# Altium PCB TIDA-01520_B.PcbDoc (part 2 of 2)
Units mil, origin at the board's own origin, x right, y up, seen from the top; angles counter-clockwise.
Board outline 2952.76 x 2362.2 mil, 2 copper layers (Top Layer, Bottom Layer), stack 62 mil thick; 118 components, 52 nets, 283 pads, 133 vias.
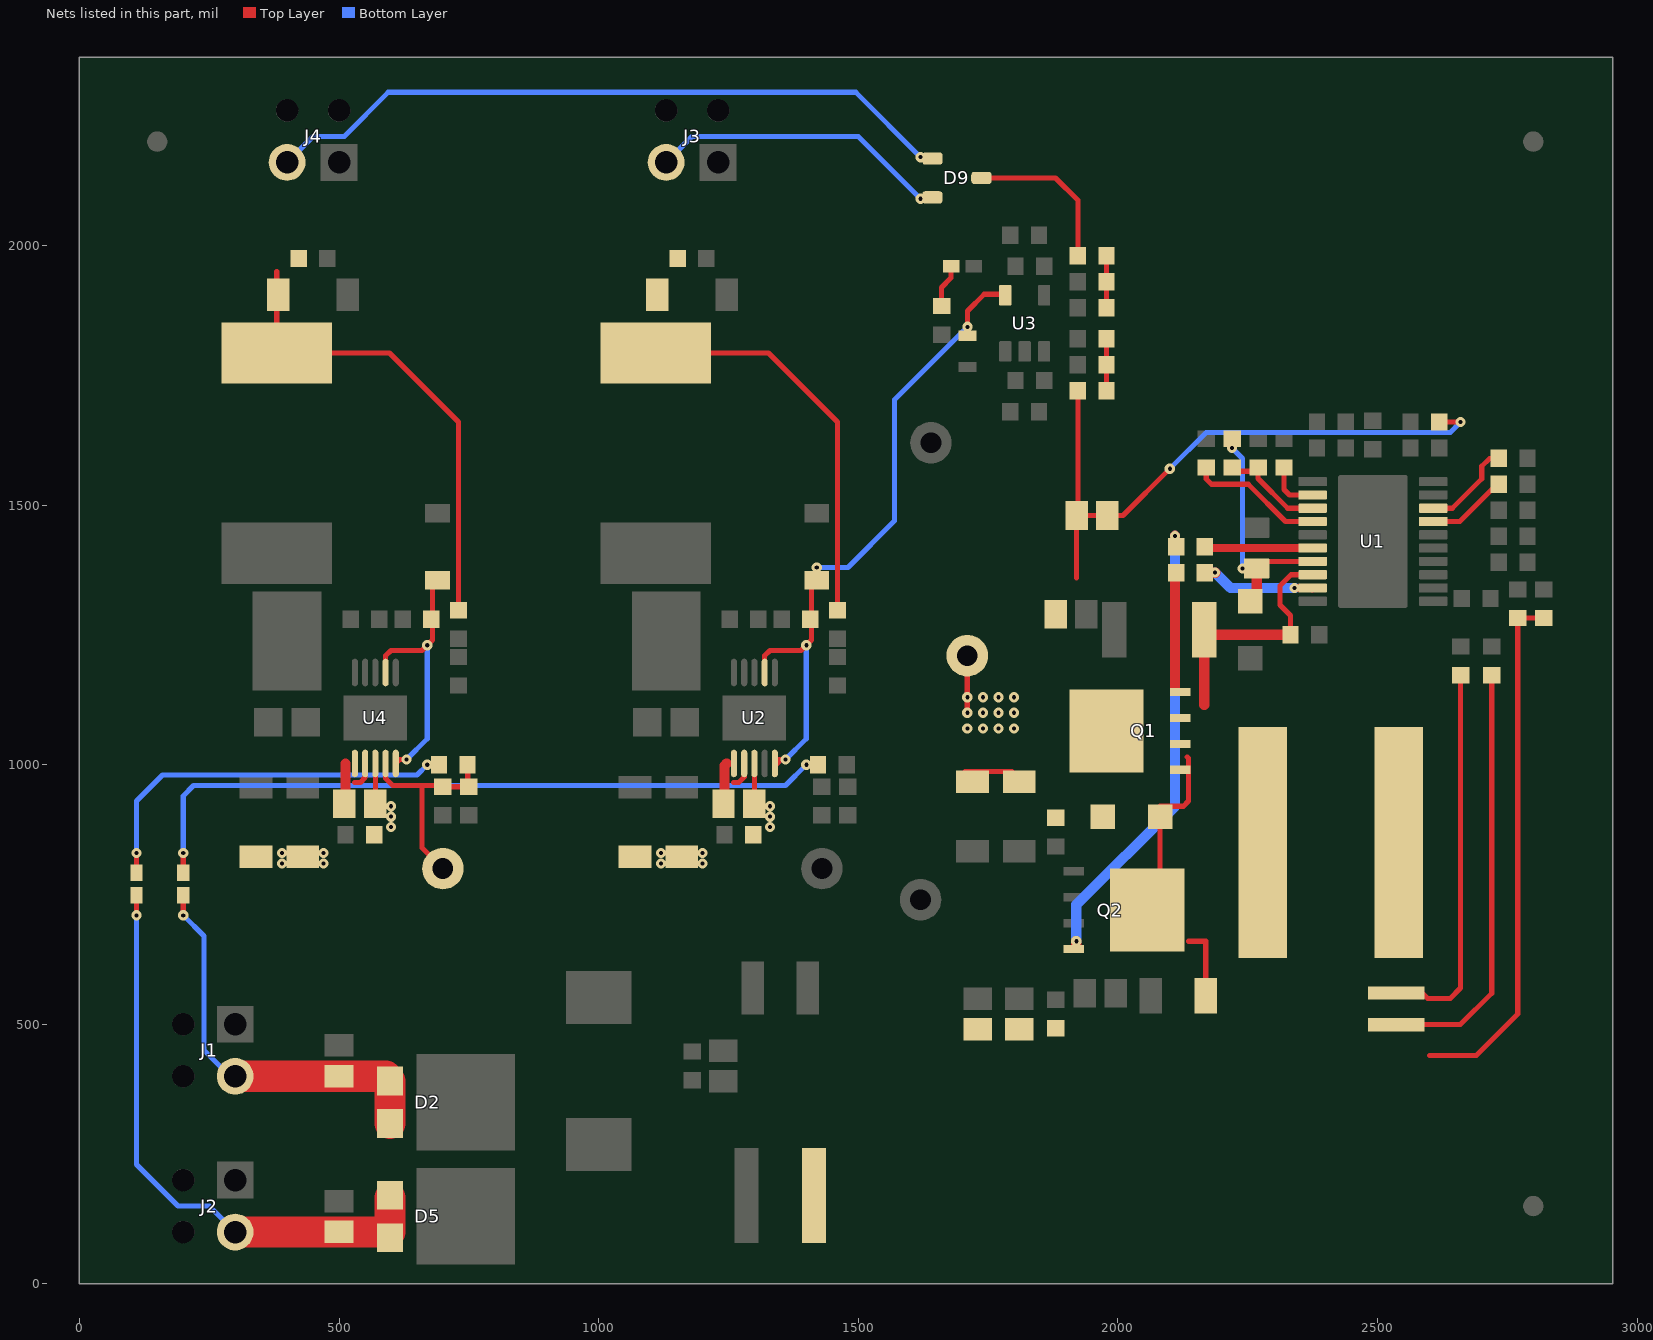
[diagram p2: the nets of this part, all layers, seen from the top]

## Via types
v1: diameter 19.68, hole 7.87, Top Layer to Bottom Layer, tented both sides, 124 vias
v2: diameter 19.68, hole 7.87, Top Layer to Bottom Layer, 9 vias

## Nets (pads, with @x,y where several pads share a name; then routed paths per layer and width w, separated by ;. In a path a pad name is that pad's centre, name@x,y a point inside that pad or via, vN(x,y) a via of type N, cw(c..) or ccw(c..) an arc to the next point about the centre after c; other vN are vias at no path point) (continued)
NetC40_1: C40.1 R36.1 R37.1 TP5.1 U4.9 | length 420.8
  Top Layer w10: U4.9@589.69,1002.4 589.69,973.79 603.48,960 R37.1@702.44,960 ; 660,960 660,840 TP5.1@700,800 ; R37.1@697.44,955 R37.1@700,957.56 C40.1@750,957.56 C40.1@752.56,960.12 ; C40.1@748.05,960.12 R36.1@748.05,1000
NetD8_1: D8.1 R23.2 | length 1373.2
  Top Layer w10: D8.1@200,791.65 v1(200,830)
  Bottom Layer w10: v1(200,830) 200,940 220,960 1360.04,960.04 v1(1400,1000)
NetD9_3: D9.3 R26.2 | length 310.5
  Top Layer w10: D9.3@1737.24,2130 1880,2130 1922.91,2087.09 1922.91,2030 R26.2@1922.91,1980
NetD11_2: D11.2 R29.2 | length 90
  Top Layer w10: R29.2@1660.47,1877.56 1660.47,1919.31 1678.82,1937.66 D11.2@1678.82,1960
NetD13_1: D13.1 R36.2 | length 749.8
  Top Layer w10: D13.1@110,791.65 v1(110,830) ; v1(670,1000) R36.2@692.44,1000
  Bottom Layer w10: v1(110,830) 110,930 160,980 650,980 v1(670,1000)
NetL1_1: L1.1 R2.2 R9.2 | length 688.9
  Top Layer w10: R2.2@2586.14,560.51 2596.65,550 2640,550 2660,570 R9.2@2660,1172.44
NetQ1_4: Q1.4 R12.2 | length 230
  Top Layer w20: Q1.4@2110,1145 R12.2@2110,1375
NetQ2_4: Q2.4 R11.2 | length 887.2
  Top Layer w20: Q2.4@1920,650.43 v1(1920,660) ; R11.2@2110,1422.44 v1(2110,1440.67)
  Bottom Layer w20: v1(1920,660) 1920,730 2110,920 v1(2110,1440.67)
NetR11_1: R11.1 U1.16 | length 208.6
  Top Layer w10: R11.1@2167.56,1420 R11.1@2170.35,1417.2
  Top Layer w16: R11.1@2170.35,1417.2 U1.16@2375,1417.2
NetR12_1: R12.1 U1.19 | length 220
  Top Layer w10: U1.19@2374.57,1340 U1.19@2375,1340.43
  Top Layer w16: v1(2340.26,1340.43) 2374.13,1340.43 U1.19@2374.57,1340
  Top Layer w20: R12.1@2167.56,1370 v1(2187.24,1370)
  Bottom Layer w20: v1(2187.24,1370) 2216.81,1340.43 v1(2340.26,1340.43)
NetR16_1: R16.1 R17.1 U1.13 | length 195.3
  Top Layer w10: R17.1@2220,1565.24 R16.1@2260,1565.24 ; R16.1@2263.94,1575.24 2270,1569.18 2270,1551.14 2327.17,1493.98 U1.13@2375,1493.98
NetR18_2: R18.2 U1.14 | length 256.6
  Top Layer w10: R18.2@2163.94,1565.24 2170,1559.18 2170,1550 2180,1540 2251.14,1540 2322.76,1468.39 U1.14@2375,1468.39
NetR19_2: R19.2 U1.12 | length 107.1
  Top Layer w10: R19.2@2313.94,1575.24 2320,1569.18 2320,1530 2330.43,1519.57 U1.12@2375,1519.57
NetR20_2: R20.2 U1.8 | length 194.2
  Top Layer w10: U1.8@2607.28,1493.98 2643.98,1493.98 2700.87,1550.87 2700.87,1574.73 2716.14,1590 R20.2@2733.58,1590 R20.2@2743.58,1580
NetR21_1: R21.1 U2.6 U2.7 | length 114.9
  Top Layer w10: 1260,965.98 1270,965.98 1280.32,976.3 U2.7@1280.32,1002.4
  Top Layer w20: R21.1@1242.44,940 1242.44,998.03 1246.81,1002.4
NetR26_1: R26.1 R27.2 R28.1 | length 100
  Top Layer w10: R27.2@1978.03,1880 R28.1@1978.03,1930 R26.1@1978.03,1980
NetR30_1: R30.1 R31.1 R33.2 | length 100
  Top Layer w10: R31.1@1978.03,1720 R30.1@1978.03,1770 R33.2@1978.03,1820
NetR34_1: R34.1 U4.6 U4.7 | length 113.8
  Top Layer w10: 530,965.98 541.14,965.98 550.32,975.16 U4.7@550.32,1002.4
  Top Layer w20: 512.4,1002.4 R34.1@512.44,940
SS: C18.1 U1.7 | length 171.4
  Top Layer w10: U1.7@2611.14,1472.24 U1.7@2607.28,1468.39 2658.39,1468.39 2730,1540 C18.1@2743.58,1540
SW_BOOST: C11.2 D1.2 L1.2 Q1.1 Q1.2 Q1.3 Q2.5 R1.1 R4.2 U1.18 | length 902.4
  Top Layer w10: Q2.5@2057.83,750 2081.26,773.43 2081.26,920 2126.14,920 2136.14,930 2136.14,1012.28 2133.43,1015 ; 2136.14,660 2169.29,660 R4.2@2169.29,580 ; C11.2@2332.44,1250 2332.44,1287.56 2312.44,1307.56 2312.44,1344.74 2333.72,1366.02 U1.18@2375,1366.02
  Top Layer w20: 2166.61,1115 R1.1@2166.61,1260 ; R1.1@2190,1250 C11.2@2335,1250
V+: C3.1 C4.1 C5.1 L2.2 R2.1 R5.2 R6.2 R8.2 | length 1791.1
  Top Layer w10: R2.1@2586.14,499.49 2659.49,499.49 2720,560 2720,1162.44 R8.2@2710,1172.44 ; 2600,440 2690,440 2770,520 R6.2@2770,1282.44 R5.2@2820,1282.44
VCC: C12.2 D4.2 R17.2 U1.17 | length 395.3
  Top Layer w10: C12.2@2274.92,1391.61 U1.17@2375,1391.61
  Top Layer w20: D4.2@2267.14,1327.26 C12.2@2267.14,1377.83
  Bottom Layer w10: v1@2218,1606 v1@2221,1609 ; v1(2220,1610) 2240,1590 v1(2240,1377.83)
VCC_B1: C19.1 C29.1 D6.2 U2.2 U2.10 U3.5 | length 1261.1
  Top Layer w10: U2.2@1319.69,1177.6 1319.69,1209.69 1330,1220 1390,1220 v1(1400,1230) 1410,1240 D6.2@1410,1345.53 ; U2.10@1339.37,1002.4 1341.77,1000 v1@1351.77,1010 ; 1346.97,1010 v1@1351.77,1010 ; v1(1360,1010) v1@1351.77,1010 ; C29.1@1710.47,1825.86 v1(1710.47,1843.36) 1710.47,1873.73 1742.74,1906 1781.2,1906 U3.5@1783.07,1904.13
  Bottom Layer w10: v1(1360,1010) 1400,1050 v1(1400,1230) ; v1(1420,1380) 1480,1380 1570,1470 1570,1702.89 v1(1710.47,1843.36)
VCC_B2: C31.1 D10.2 U4.2 U4.10 | length 515
  Top Layer w10: U4.2@589.69,1177.6 589.69,1209.69 600,1220 660,1220 680,1240 680,1280 680,1345.53 D10.2@690,1355.53 ; U4.10@609.37,1002.4 616.97,1010 v1(630,1010)
  Bottom Layer w10: v1(630,1010) 670,1050 v1(670,1230)
VIN1: C30.1 D2.1 D2.2 D8.2 J1.2 | length 767.5
  Top Layer w10: v1(200,710) D8.2@200,748.35
  Top Layer w60: J1.2@300,400 D2.2@590,400 ; D2.1@597.95,309.06 D2.2@597.95,390.94
  Bottom Layer w10: v1(200,710) 240,670 240,450 290,400 J1.2@300,400
VIN2: C41.1 D5.1 D5.2 D13.2 J2.2 | length 1126.4
  Top Layer w10: v1(110,709.96) D13.2@110,748.35
  Top Layer w60: J2.2@300,100 597.95,100 D5.2@597.95,166.22
  Bottom Layer w10: v1(110,709.96) 110,230 190,150 250,150 J2.2@300,100
VOUT_B1: C24.1 C25.1 D9.2 J3.2 L3.2 R22.2 | length 1325.5
  Top Layer w10: L3.2@1110,1792.91 1327.09,1792.91 1460,1660 R22.2@1460,1300
  Bottom Layer w10: J3.2@1130,2160 1180,2210 1500,2210 v1(1620,2090)
VOUT_B2: C37.1 C38.1 D9.1 J4.2 L4.2 R35.2 | length 2255.5
  Top Layer w10: 380,1950 L4.2@380,1802.91 ; L4.2@384.02,1806.93 L4.2@380,1802.91 ; R35.2@730,1300 730,1660 597.09,1792.91 L4.2@380,1792.91 L4.2@380,1802.91
  Bottom Layer w10: J4.2@400,2160 450,2210 510,2210 595,2295 1495,2295 v1(1620,2170)
VOUT_BOOST: C6.1 C7.1 C8.1 C9.1 C21.1 C22.1 C23.1 C34.1 C35.1 C36.1 D1.1 Q1.5 R7.1 R7.2 R10.2 R21.2 R31.2 R34.2 TP1.1 U2.8 U4.8 | length 1561.4
  Top Layer w10: R34.2@570,920 U4.8@570,1002.4 ; R21.2@1300,920 U2.8@1300,1002.4 ; C7.1@1706.14,986.93 C8.1@1796.14,986.93 ; v1(1710,1100) TP1.1@1710,1190 ; 1920,1360 1920.47,1360.47 R7.2@1920.47,1480 ; R31.2@1922.91,1720 1922.91,1482.44 R7.2@1920.47,1480 ; v1(2100,1570) 2010,1480 R7.1@1979.53,1480 R7.2@1920.47,1480 ; R10.2@2618.7,1660 v1(2660,1660)
  Bottom Layer w10: v1(2100,1570) 2170,1640 2640,1640 v1(2660,1660)
  other v1: 390,810 470,810 1120,810 1200,810 390,830 470,830 1120,830 1200,830 600,880 1330,880 600,900 1330,900 600,920 1330,920 1710,1070 1740,1070 1770,1070 1800,1070 1740,1100 1770,1100 1800,1100 1710,1130 1740,1130 1770,1130 1800,1130
pads on no net: FID1.1 FID2.1 FID3.1 J1.MH1 J1.MH2 J2.MH1 J2.MH2 J3.MH1 J3.MH2 J4.MH1 J4.MH2 U1.1 U1.21@2491.14,1430 U2.0 U4.0

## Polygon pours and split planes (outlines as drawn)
NetC1_1 on Bottom Layer "BOTTOM_LAYER_NETC1_1_P021" (solid, remove dead copper, pour order 21): 1270,50 1310,90 1310,350 1250,410 390,410 360,380 360,90 400,50
VOUT_BOOST on Bottom Layer "BOTTOM_LAYER_VOUT_BOOST_P009" (solid, remove dead copper, pour order 9): 2080,920 2000,840 1736.14,840 1706.14,810 1536.14,640 270,640 220,690 220,950 1380,950 1570,1140 1570,1418.84 1591.16,1440 2080,1440
GND on Bottom Layer "BOTTOM_LAYER_GND_P012" (solid, remove dead copper, pour order 12): 900,980 180,980 50,1110 50,2110 130,2190 900,2190
GND on Bottom Layer "BOTTOM_LAYER_GND_P010" (solid, remove dead copper, pour order 10): 1550,980 870,980 870,2190 1480,2190 1550,2120
GND on Bottom Layer "BOTTOM_LAYER_GND_P019" (solid, remove dead copper, pour order 19): 2900,100 2850,50 1430,50 1380,100 1380,520 1580,720 1580,2260 1630,2310 2850,2310 2900,2260
VOUT_BOOST on Top Layer "TOP_LAYER_VOUT_BOOST_P003" (solid, remove dead copper, pour order 3): 640,910 580,970 560,970 550,960 550,879.33 520.67,850 300,850 300,740 570,740 640,810
NetR21_1 on Top Layer "TOP_LAYER_NETR21_1_P001" (solid, remove dead copper, pour order 1): 1220,920 1220,1000.49 1249.51,1030 1265.16,1030 1265.16,955.65 1259.51,950 1259.51,920
NetR34_1 on Top Layer "TOP_LAYER_NETR34_1_P000" (solid, remove dead copper, pour order 0): 490,920 490,1000 520,1030 535.16,1030 535.16,955.16 530,950 530,920
BAT_GND on Top Layer "TOP_LAYER_BAT_GND_P020" (solid, remove dead copper, pour order 20): 1260,430 1310,480 1310,600 1290,620 100,620 50,570 50,100 100,50 530,50 530,430
NetC1_1 on Top Layer "TOP_LAYER_NETC1_1_P017" (solid, remove dead copper, pour order 17): 1270,50 1310,90 1310,360 1260,410 570,410 570,50
VOUT_BOOST on Top Layer "TOP_LAYER_VOUT_BOOST_P008" (solid, remove dead copper, pour order 8): 2060,950 1990,880 1750,880 1650,980 1650,1340 1690,1380 2020,1380 2060,1340
SW_BOOST on Top Layer "TOP_LAYER_SW_BOOST_P014" (solid, remove dead copper, pour order 14): 2240,1120 2090,1120 2080,1110 2080,940 1980,840 1980,620 2000,600 2260,600 2290,630 2290,1070
GND on Top Layer "TOP_LAYER_GND_P013" (solid, remove dead copper, pour order 13): 2770,1370.09 2770,1610.67 2760.67,1620 2720,1620 2690,1590 2690,1550 2659.57,1519.57 2625.59,1519.57 2625.59,1615.59 2670,1660 2670,1690 2350,1690 2340,1680 2340,1610 2140,1610 2090,1660 2090,1780 2140,1830 2850,1830 2900,1780 2900,1380 2890.09,1370.09
GND on Top Layer "TOP_LAYER_GND_P011" (solid, remove dead copper, pour order 11): 1959.78,530 1410,530 1300,640 100,640 50,690 50,2260 100,2310 1580,2310 1630,2260 1630,970 1740,860 1959.78,860
V+ on Top Layer "TOP_LAYER_NETC3_1_P015" (solid, remove dead copper, pour order 15): 2610,510 1430,510 1380,460 1380,100 1430,50 1480,50 1730,300 2520,300 2610,390
NetL1_1 on Top Layer "TOP_LAYER_NETL1_1_P016" (solid, remove dead copper, pour order 16): 2610,660 2610,540 2480,540 2480,660
NetC33_2 on Top Layer "TOP_LAYER_NETC33_2_P007" (solid, remove dead copper, pour order 7): 520.31,1210.31 490,1240.63 490,1470 270,1470 270,1350 330,1290 330,1140 480,1140 499.13,1140 500,1140 508.04,1148.04 540,1148.04 540,1210.31
NetC20_2 on Top Layer "TOP_LAYER_NETC20_2_P006" (solid, remove dead copper, pour order 6): 1220,1249.99 1220,1470 1000,1470 1000,1350 1059.06,1290.95 1059.06,1140 1210,1140 1229.13,1140 1230,1140 1238.04,1148.04 1270,1148.04 1270,1219.81 1250,1220
VOUT_B2 on Top Layer "TOP_LAYER_VOUT_B2_P004" (solid, remove dead copper, pour order 4): 490,1730 490,1850 450,1890 450,2180 250.01,2180 250,1990 250,1730
VOUT_B1 on Top Layer "TOP_LAYER_VOUT_B1_P005" (solid, remove dead copper, pour order 5): 1220,1730 1220,1850 1180,1890 1180,2180 980.01,2180 980,1990 980,1730
VOUT_BOOST on Top Layer "TOP_LAYER_VOUT_BOOST_P002" (solid, remove dead copper, pour order 2): 1370,905.62 1305.62,970 1290,970 1280,960 1280,879.33 1250.67,850 1030,850 1030,740 1318.39,740 1370,791.61

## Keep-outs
Keep-Out Layer:
  text ".Layer_Name" at 577,-858.49 h60

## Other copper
Top Layer:
  text ".Layer_Name" at 577,-858.49 h60
Bottom Layer:
  text ".Layer_Name" at 577,-858.49 h60

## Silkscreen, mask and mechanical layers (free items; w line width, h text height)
Top Overlay:
  lines w8: 1570,1535.86 2020.47,1535.86 2020.47,2205.86 1570,2205.86 1570,1535.86
  text "+" at 390,2310 h40
  text "-" at 490,2310 h40
  text "+" at 1120,2310 h40
  text "-" at 1220,2310 h40
  text "CH2" at 600,2260 h40
  text "CH1" at 1330,2260 h40
  text "Pre-Boost Control" at 1550,2230 h30
  text "'.PRJ_Number' Rev.'.PCB_Rev'" at 2290,2050 h40
  text "'.PRJ_Title'" at 2300,1980 h30
  text "-" at 110,490 h40
  text "IN1" at 30,430 h40
  text "+" at 110,370 h40
  text "6-18V" at 30,280 h30
  text "-" at 110,190 h40
  text "IN2" at 30,130 h40
  text "+" at 110,70 h40
  text ".Layer_Name" at 577,-858.49 h60
Bottom Overlay:
  text ".Layer_Name" at 577,-858.49 h60
Top Paste:
  text ".Layer_Name" at 577,-858.49 h60
Bottom Paste:
  text ".Layer_Name" at 577,-858.49 h60
Top Solder:
  text ".Layer_Name" at 577,-858.49 h60
  text ".Layer_Name" at 577,-858.49 h60
Bottom Solder:
  text ".Layer_Name" at 577,-858.49 h60
Drill Guide:
  text ".Layer_Name" at 577,-858.49 h60
M1 Board Outline:
  the board outline again, w10
  text ".Layer_Name" at 577,-858.49 h60
M2 Board Dimensions:
  rectangle: 0,-275 125,-150
  rectangle: 125,-400 500,-275
  lines w7: 0,-275 1000,-275 ; 125,-400 125,-150 ; 250,-400 250,-150 ; 500,-400 500,-150 ; 750,-400 750,-150 ; 0,-400 1000,-400 1000,-150 0,-150 0,-400
  text ".Layer_Name" at 577,-858.49 h60
M3 3D STEP Top:
  text ".Layer_Name" at 577,-858.49 h60
M4 3D STEP Bottom:
  text ".Layer_Name" at 577,-858.49 h60
M5 Assembly Top:
  lines w10: -292,-930.17 6308,-930.17 ; -292,-726.83 6310,-726.83 ; -292,-523.5 -292,-1133.5 3713,-1133.5 6310,-1133.5 6310,-523.5 -291.5,-523.5 -291.5,-1133.5 1284,-1133.5 ; 2173,-1133.5 2173,-523.5 ; 3440,-726.83 3440,-523.5 ; 4280,-726.83 4280,-523.5 ; 4902,-1140 4902,-937.17
  text "COMPONENTS MARKED 'DNP' SHOULD NOT BE POPULATED." at 1153.5,-318.5 h60
  text "ASSEMBLY VARIANT:" at 1153,-434 h60
  text ".VariantName" at 2189,-434 h60
  text "PCB VIEWED FROM TOP SIDE" at -228.5,-655.67 h60
  text "BOARD #:" at 2248,-655.67 h60
  text ".PRJ_Number" at 2793.5,-655.67 h60
  text "REV:" at 3638,-655.67 h60
  text ".PCB_Rev" at 3929.5,-655.67 h60
  text "SVN REV:" at 4476,-655.67 h60
  text ".VersionControl_RevNumber" at 4982,-655.67 h60
  text "TID #:" at 2248,-859 h60
  text ".TID" at 2793.5,-859 h60
  text "PLOT NAME =" at -228.5,-1064.34 h60
  text ".plot_File_Name" at 577,-1064.34 h60
  text "GENERATED    :" at 2250,-1064.34 h60
  text ".Print_Date" at 3119.5,-1064.34 h60
  text ".Print_Time" at 3848.5,-1064.34 h60
  text "TEXAS INSTRUMENTS" at 5113,-1064.34 h60
M6 Assembly Bottom:
  lines w10: -292.5,-727.33 6309.5,-727.33 ; -290.5,-930.67 6309.5,-930.67 ; 1115.5,-1140.5 1115.5,-937.67 ; 1737.5,-727.33 1737.5,-524 ; 2577.5,-727.33 2577.5,-524 ; 3844.5,-1134 3844.5,-524 ; 4733.5,-1134 6309,-1134 6309,-524 -292.5,-524 -292.5,-1134 2304.5,-1134 6309.5,-1134 6309.5,-524
  text "COMPONENTS MARKED 'DNP' SHOULD NOT BE POPULATED." at 6102,-318 h60
  text ".VariantName" at 5058,-434 h60
  text "ASSEMBLY VARIANT:" at 6097,-434 h60
  text ".VersionControl_RevNumber" at 1035.5,-656.17 h60
  text "SVN REV:" at 1541.5,-656.17 h60
  text ".PCB_Rev" at 2088,-656.17 h60
  text "REV:" at 2379.5,-656.17 h60
  text ".PRJ_Number" at 3224,-656.17 h60
  text "BOARD #:" at 3769.5,-656.17 h60
  text "PCB VIEWED FROM BOTTOM SIDE" at 6246,-656.17 h60
  text ".TID" at 3224,-859.5 h60
  text "TID #:" at 3769.5,-859.5 h60
  text "TEXAS INSTRUMENTS" at 904.5,-1064.84 h60
  text ".Print_Time" at 2169,-1064.84 h60
  text ".Print_Date" at 2898,-1064.84 h60
  text "GENERATED    :" at 3767.5,-1064.84 h60
  text ".plot_File_Name" at 5440.5,-1064.84 h60
  text "PLOT NAME =" at 6246,-1064.84 h60
M9 Title Sheet:
  drawing of 57 lines, arcs and shapes, not listed
  text "1" at 739.84,8036.5 h70
  text "2" at 3235.5,8036.5 h70
  text "3" at 5724.84,8036.5 h70
  text "4" at 8231.51,8036.5 h70
  text "5" at 10730.5,8036.5 h70
  text "6" at 13235.5,8036.5 h70
  text "A" at -416.5,6893.5 h70
  text "A" at 14383.5,6893.5 h70
  text "B" at -416.5,4513.5 h70
  text "B" at 14383.5,4513.5 h70
  text "C" at -416.5,2138.5 h70
  text "C" at 14383.5,2138.5 h70
  text "PROJECT TITLE:" at 11343.5,277.5 h45
  text ".PRJ_Title" at 11393.5,144.17 h70
  text "DESIGNED FOR:" at 11343.5,-23.5 h45
  text ".PRJ_Customer" at 11393.5,-163.5 h70
  text "D" at -416.5,-231.5 h70
  text "D" at 14383.5,-231.5 h70
  text "FILE NAME:" at 11343.5,-323.5 h45
  text ".PCB_File_Name_No_Path" at 11393.5,-443.5 h70
  text "Texas Instruments (TI) and/or its licensors do not warrant the accuracy or completeness of this specification" at 6374,-605.34 h45
  text "ENGINEER:" at 11343.5,-613.5 h45
  text "LAYOUT BY:" at 12848.5,-613.5 h45
  text "or any information contained therein. TI and/or its licensors do not warrant that this design will meet" at 6329.01,-718 h45
  text ".PRJ_Engineer" at 11393.5,-768.49 h70
  text ".PCB_Layout" at 12899,-768.49 h70
  text "the specifications, will be suitable for your application or fit for any particular purpose, or will operate in" at 6329.01,-830.67 h45
  text ".Layer_Name" at 577,-858.49 h60
  text "ALTIUM DESIGNER VERSION:" at 12848.5,-923.5 h45
  text "an implementation. TI and/or its licensors do not warrant that the design is production worthy. You should" at 6329.01,-943.33 h45
  text "completely validate and test your design implementation to confirm the system functionality for your application." at 6374,-1056 h45
  text ".print_Scale" at 11393.5,-1056.83 h70
  text ".Application_BuildNumber" at 12899,-1056.83 h70
  text "1" at 739.84,-1263.5 h70
  text "2" at 3235.5,-1263.5 h70
  text "3" at 5724.84,-1263.5 h70
  text "4" at 8231.51,-1263.5 h70
  text "5" at 10730.5,-1263.5 h70
  text "6" at 13235.5,-1263.5 h70
M10 Fab Notes:
  drawing of 173 lines, arcs and shapes, not listed
  text "DESIGN INFORMATION" at 12378.02,6201 h60
  text "MIN. TRACK WIDTH:" at 11733.46,6021 h60
  text "10" at 12829.7,6021 h60
  text "MIL" at 12984.46,6021 h60
  text "MIN. CLEARANCE:" at 11733.46,5889 h60
  text "0.2" at 12769.7,5889 h60
  text "mm" at 12984.46,5889 h60
  text "19.685" at 12630,5760 h60
  text "MIN. VIA PAD SIZE:" at 11733.46,5757 h60
  text "MIL" at 12984.46,5757 h60
  text "0.05mm (2MIL)" at 12428.46,5615.29 h60
  text "MINIMUM ANNULAR RING" at 11404.23,5611 h60
  text "EXTERNAL" at 13136.46,5611 h60
  text "PER" at 11604.23,5493 h60
  text "IPC-D-275 CLASS 2 LEVEL C" at 11824.23,5493 h60
  text "MIL, HOLES" at 13312.46,5380.71 h60
  text "+/-" at 12920,5380 h60
  text "+/-" at 13774,5380 h60
  text "REGISTRATION TOLERANCES:" at 11404.23,5375 h60
  text "METAL" at 12604,5375 h60
  text "5" at 13180.2,5375 h60
  text "3" at 14013.2,5375 h60
  text "MIL" at 14129.46,5375 h60
  text "+/-" at 13774,5262 h60
  text "HOLE SIZE TOLERANCE (UNLESS OTHERWISE SPECIFIED):" at 11404.23,5257 h60
  text "3" at 14013.2,5257 h60
  text "MIL" at 14129.46,5257 h60
  text "MATERIAL:" at 11329.46,5047.54 h60
  text "FR-4 High Tg" at 12315.9,4907.21 h60
  text "FR-408" at 11750.46,4898.64 h60
  text "OTHER" at 13238.46,4898.64 h60
  text "X" at 12161,4895 h60
  text "62 MIL (1.6mm) +/-10%" at 12070.56,4735.92 h60
  text "THICKNESS:" at 11404.23,4731.64 h60
  text "X" at 11942.4,4731.64 h60
  text "OTHER" at 13355.46,4731.64 h60
  text "TOLERANCE:" at 11404.23,4573.64 h60
  text "X" at 12243.53,4573.64 h60
  text "ANSI IPC-6012 TYPE 3 CLASS 2" at 12430.48,4573.64 h60
  text "OTHER +/-" at 12430.46,4417.64 h60
  text "BOW & TWIST:" at 11404.23,4260.64 h60
  text "X" at 12243.53,4260.64 h60
  text "ANSI IPC-6012 TYPE 3 CLASS 2" at 12430.48,4260.64 h60
  text "OTHER +/-" at 12430.46,4102.13 h60
  text "DRILLING:" at 11329.46,3963.64 h60
  text "REFERENCE:" at 11404.23,3846.64 h60
  text "X" at 12052.46,3846.64 h60
  text "AS SHOWN" at 12239.46,3846.64 h60
  text "X" at 12953.46,3846.64 h60
  text "NC_DRILL FILES" at 13090.46,3846.64 h60
  text "PTH COPPER THICKNESS:" at 11404.23,3688.64 h60
  text "X" at 12534.46,3688.64 h60
  text "20-30 um" at 12671.46,3688.64 h60
  text "OTHER" at 13388.46,3688.64 h60
  text "BOARD FINISH:" at 11329.46,3529.64 h60
  text "SILKSCREEN:" at 11484.68,3411.64 h60
  text "X" at 12433.46,3411.64 h60
  text "TOP" at 12559.46,3411.64 h60
  text "BOTTOM" at 13070.46,3411.64 h60
  text "SILKSCREEN COLOR:" at 11484.68,3244.64 h60
  text "X" at 12432.42,3244.64 h60
  text "WHITE" at 12559.46,3244.64 h60
  text "OTHER" at 13070.46,3244.64 h60
  text "X" at 12563.42,3085.44 h60
  text "GREEN" at 12690.46,3085.44 h60
  text "OTHER" at 13308.46,3085.44 h60
  text "SOLDER RESIST COLOR:" at 11484.68,3074.64 h60
  text "X" at 12563.42,2915.44 h60
  text "MATTE" at 12690.46,2915.44 h60
  text "SEMI-GLOSS" at 13308,2914.8 h60
  text "IMMERSION GOLD (ENIG)" at 12390.46,2726.92 h60
  text "ENEPIG" at 13728,2723.64 h60
  text "SURFACE FINISH:" at 11329.46,2722.64 h60
  text "X" at 12203.51,2722.64 h60
  text "IMM. TIN/SILVER OR EQUIV" at 11659,2565.64 h60
  text "OTHER" at 13090.46,2565.64 h60
  text "ARRAY/PANEL:" at 11329.46,2386.64 h60
  text "CUT AND TRIM PER M1 BOARD OUTLINE" at 12390.46,2382.35 h60
  text "N.C. ROUTE" at 12390.46,2230.64 h60
  text "X" at 13069.46,2230.64 h60
  text "V. SCORE" at 13256.46,2230.64 h60
  text "CERTIFICATION:" at 11329.46,2093.64 h60
  text "MATERIALS AND WORKMANSHIP FOR ALL PCBS" at 12054.46,2093.64 h60
  text "TO MEET OR EXCEED THE REQUIREMENTS OF:" at 12054.46,1995.64 h60
  text "X" at 11680.96,1859.13 h60
  text "ANSI IPC-A-600F CLASS ->" at 11819.96,1859.13 h60
  text "X" at 13459.02,1859.13 h60
  text "2" at 13577.96,1859.14 h60
  text "1" at 13262.96,1857.64 h60
  text "3" at 13931.96,1857.64 h60
  text "X" at 12495.02,1699.64 h60
  text "RoHS" at 12631.96,1699.64 h60
  text "OTHER" at 13276.36,1699.64 h60
  text "PER ORDER" at 13673.42,1699.64 h60
  text "ALL BOARDS MUST MEET OR EXCEED UL94-V0 REQUIREMENTS." at 11357,1534 h60
  text "PCB MUST BEAR THE UL94V-0 UL REGISTERED MATERIAL ID NUMBER" at 11357,1414 h60
  text "ADDITIONAL REQUIREMENTS:" at 11329.46,1240.64 h60
  text "MICROSECTION:" at 11404.23,1125.64 h60
  text "YES" at 12309.96,1125.64 h60
  text "REQUIRED" at 13171.46,969.49 h60
  text "BARE BOARD ELEC. TEST:" at 11404.23,966.64 h60
  text "NONE" at 12709.96,966.64 h60
  text "X" at 13044.46,966.64 h60
  text "PER ORDER" at 13763.46,966.64 h60
  text ".Layer_Name" at 577,-858.49 h60
M11 Gerber Information:
  lines w10: -292,-930.17 6308,-930.17 ; -292,-726.83 6310,-726.83 ; -292,-523.5 -292,-1133.5 3713,-1133.5 6310,-1133.5 6310,-523.5 -291.5,-523.5 -291.5,-1133.5 1284,-1133.5 ; 2173,-1133.5 2173,-523.5 ; 3440,-726.83 3440,-523.5 ; 4280,-726.83 4280,-523.5 ; 4902,-1140 4902,-937.17
  text "ALL ARTWORK VIEWED FROM TOP SIDE" at -228.5,-655.67 h60
  text "BOARD #:" at 2248,-655.67 h60
  text ".PRJ_Number" at 2793.5,-655.67 h60
  text "REV:" at 3638,-655.67 h60
  text ".PCB_Rev" at 3929.5,-655.67 h60
  text "SVN REV:" at 4476,-655.67 h60
  text ".VersionControl_RevNumber" at 4982,-655.67 h60
  text "LAYER NAME =" at -228.5,-858.49 h60
  text "TID #:" at 2248,-859 h60
  text ".TID" at 2793.5,-859 h60
  text "PLOT NAME =" at -228.5,-1064.34 h60
  text ".plot_File_Name" at 577,-1064.34 h60
  text "GENERATED    :" at 2250,-1064.34 h60
  text ".Print_Date" at 3119.5,-1064.34 h60
  text ".Print_Time" at 3848.5,-1064.34 h60
  text "TEXAS INSTRUMENTS" at 5113,-1064.34 h60
M12 Stackup:
  drawing of 191 lines, arcs and shapes, not listed
  text "Layer" at 9790.34,7830 h60
  text "Name" at 10200.26,7830 h60
  text "Material" at 11130,7830 h60
  text "Thickness" at 11989.77,7830 h60
  text "Constant" at 12639.6,7830 h60
  text "Board Layer Stack" at 13209.46,7830 h60
  text "1" at 9790.34,7710 h60
  text "Top Overlay" at 10200.26,7710 h60
  text "2" at 9790.34,7590 h60
  text "Top Solder" at 10200.26,7590 h60
  text "Solder Resist" at 11130,7590 h60
  text "0.40mil" at 11989.77,7590 h60
  text "3.5" at 12639.6,7590 h60
  text "3" at 9790.34,7470 h60
  text "Top Layer" at 10200.26,7470 h60
  text "Copper" at 11130,7470 h60
  text "1.40mil" at 11989.77,7470 h60
  text "4" at 9790.34,7350 h60
  text "Dielectric1" at 10200.26,7350 h60
  text "FR-4" at 11130,7350 h60
  text "59.20mil" at 11989.77,7350 h60
  text "4.8" at 12639.6,7350 h60
  text "5" at 9790.34,7230 h60
  text "Bottom Layer" at 10200.26,7230 h60
  text "Copper" at 11130,7230 h60
  text "1.40mil" at 11989.77,7230 h60
  text "6" at 9790.34,7110 h60
  text "Bottom Solder" at 10200.26,7110 h60
  text "Solder Resist" at 11130,7110 h60
  text "0.40mil" at 11989.77,7110 h60
  text "3.5" at 12639.6,7110 h60
  text "7" at 9790.34,6990 h60
  text "Bottom Overlay" at 10200.26,6990 h60
  text ".Layer_Name" at 577,-858.49 h60
M13 Component Bodies Top:
  text ".Layer_Name" at 577,-858.49 h60
M14 Component Bodies Bottom:
  text ".Layer_Name" at 577,-858.49 h60
M15 Courtyards Top:
  text ".Layer_Name" at 577,-858.49 h60
M16 Courtyards Bottom:
  text ".Layer_Name" at 577,-858.49 h60
Drill Drawing:
  circle w10: c3293.8,2216.08 r27.66
  lines w10: 3266.14,1815.04 3321.46,1815.04 3321.46,1870.36 3266.14,1870.36 3266.14,1815.04 ; 3266.14,1953.33 3279.97,1953.33 3293.8,1939.5 3307.63,1953.33 3321.46,1953.33 3307.63,1967.16 3321.46,1980.99 3307.63,1980.99 3293.8,1994.82 3279.97,1980.99 3266.14,1980.99 3279.97,1967.16 3266.14,1953.33 ; 3266.14,2063.96 3293.8,2077.79 3321.46,2063.96 3307.63,2091.62 3321.46,2119.28 3293.8,2105.45 3266.14,2119.28 3279.97,2091.62 3266.14,2063.96
  lines w12: 3216,1777.71 6294.38,1777.71 ; 3216,2275.54 6294.38,2275.54 ; 3554.17,1653.25 3554.17,2400 ; 3886.28,1653.25 3886.28,2400 ; 4523.29,1653.25 4523.29,2400 ; 4782.64,1653.25 4782.64,2400 ; 5158.06,1653.25 5158.06,2400 ; 5881.91,1653.25 5881.91,2400 ; 3216,1653.25 6294.38,1653.25 6294.38,2400 3216,2400 3216,1653.25
  text "Symbol" at 3290.68,2312.88 h72
  text "Quantity" at 3591.51,2312.88 h72
  text "Finished Hole Size" at 3923.62,2312.88 h72
  text "Plated" at 4560.62,2312.88 h72
  text "Hole Type" at 4819.98,2312.88 h72
  text "Drill Layer Pair" at 5195.4,2312.88 h72
  text "Tolerance" at 5919.25,2312.88 h72
  text "8" at 3591.51,2188.42 h60
  text "43.31mil (1.100mm)" at 3923.62,2188.42 h60
  text "NPTH" at 4560.62,2188.42 h60
  text "Round" at 4819.98,2188.42 h60
  text "Top Layer - Bottom Layer" at 5195.4,2188.42 h60
  text "133" at 3591.51,2063.96 h60
  text "7.87mil (0.200mm)" at 3923.62,2063.96 h60
  text "PTH" at 4560.62,2063.96 h60
  text "Round" at 4819.98,2063.96 h60
  text "Top Layer - Bottom Layer" at 5195.4,2063.96 h60
  text "5" at 3591.51,1939.5 h60
  text "40.00mil (1.016mm)" at 3923.62,1939.5 h60
  text "PTH" at 4560.62,1939.5 h60
  text "Round" at 4819.98,1939.5 h60
  text "Top Layer - Bottom Layer" at 5195.4,1939.5 h60
  text "8" at 3591.51,1815.04 h60
  text "43.31mil (1.100mm)" at 3923.62,1815.04 h60
  text "PTH" at 4560.62,1815.04 h60
  text "Round" at 4819.98,1815.04 h60
  text "Top Layer - Bottom Layer" at 5195.4,1815.04 h60
  text "154 Total" at 3591.51,1690.59 h60
M17 Embedded Cavity:
  text ".Layer_Name" at 577,-858.49 h60
M18 Embedded Assembly:
  text ".Layer_Name" at 577,-858.49 h60
M19 Embedded Keepout:
  text ".Layer_Name" at 577,-858.49 h60

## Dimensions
0,-400 to 1000,-400 on M2 Board Dimensions
0,0 to 0,2362.2 on M2 Board Dimensions
0,0 to 2952.76,0 on M2 Board Dimensions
